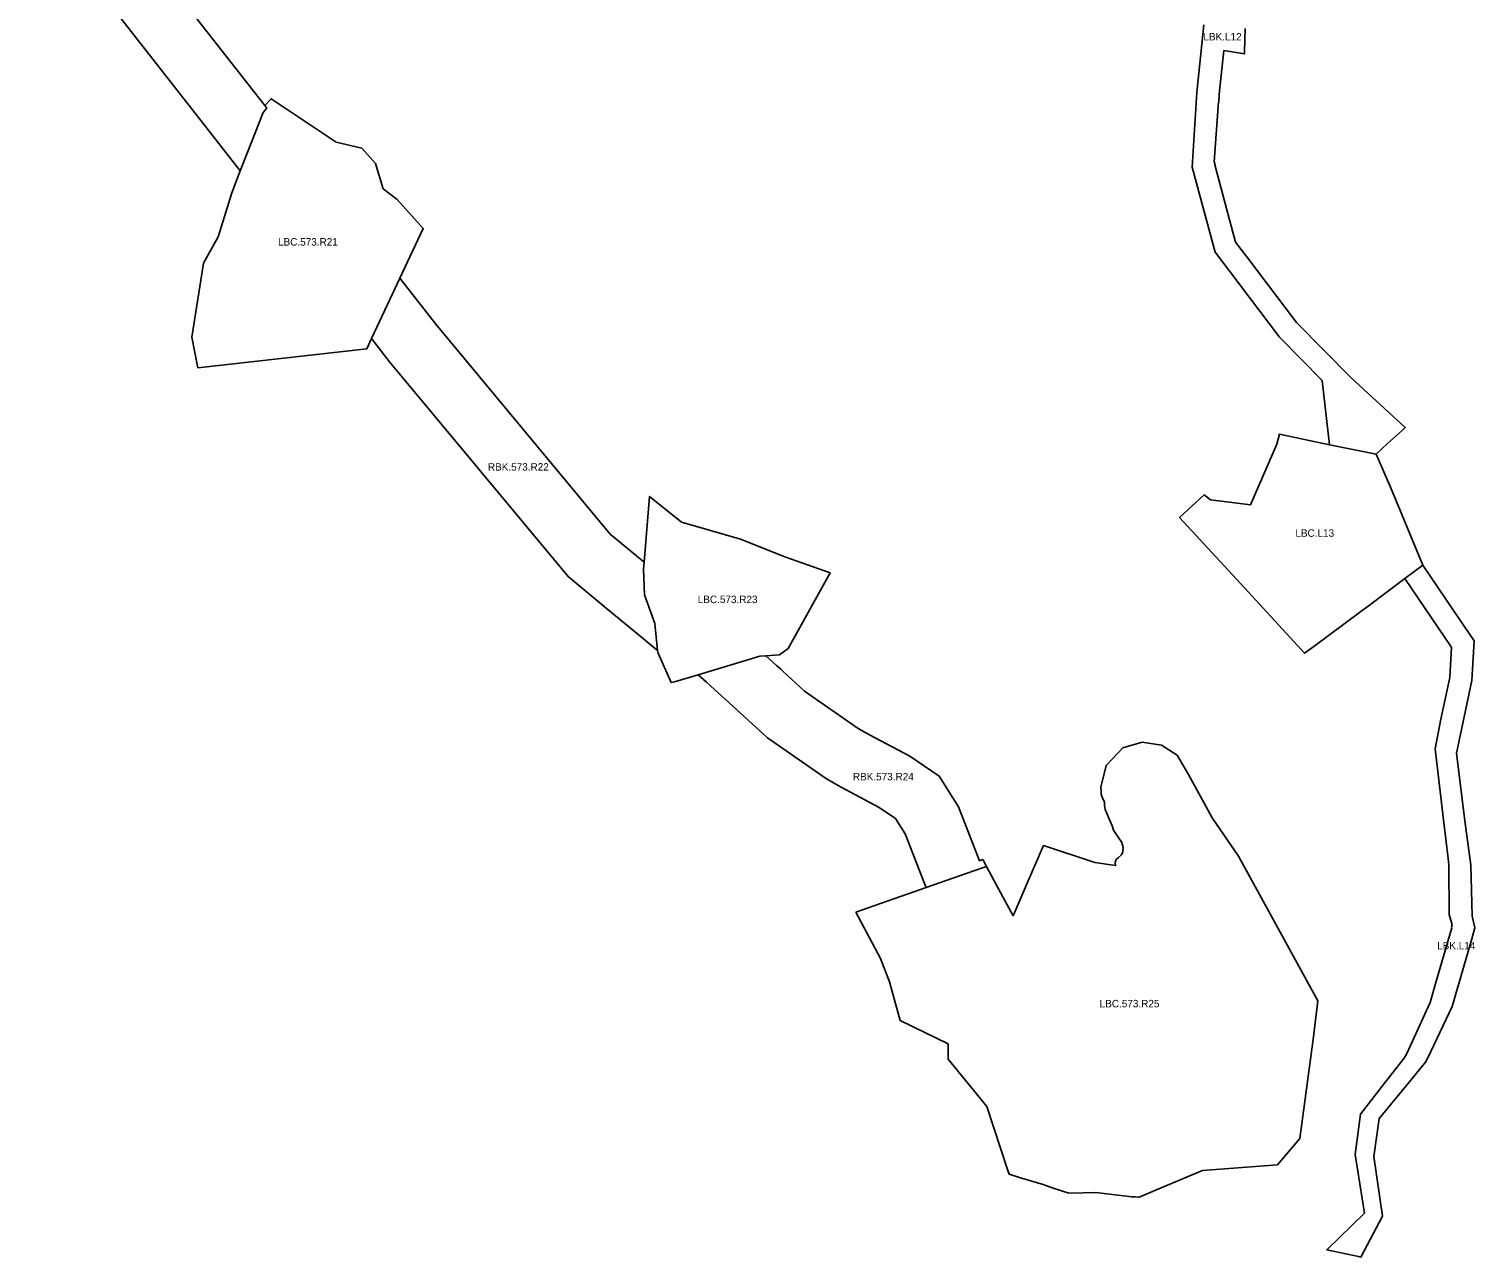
# Model space of a CAD drawing. Extents: x -450188 to -432919, y -1130252 to -1121189.
# Drawn here: x -435642 to -433700, y -1130252 to -1128604 of the extents above; entities that cross this region are included whole.
import ezdxf

# ---------------------------------------------------------------- set-up
doc = ezdxf.new("R2010")
doc.units = 0
for name, color, linetype in [('Vrstva 31', 7, 'Continuous'), ('Vrstva 32', 7, 'Continuous'), ('Vrstva 33', 7, 'Continuous'), ('Vrstva 36', 7, 'Continuous')]:
    doc.layers.add(name, color=color, linetype=linetype)

msp = doc.modelspace()

# ---------------------------------------------------------------- linework, layer by layer
at = {"layer": 'Vrstva 31'}
for p, q in [((-435322.1, -1128710.3), (-435327, -1128715.9)), ((-435324.9, -1128706.8), (-435322.1, -1128710.3))]:
    msp.add_line(p, q, dxfattribs=at)
for points in [[(-435357.8, -1128794.5), (-435405.9, -1128733.1), (-435520.6, -1128586.6), (-435605.8, -1128468.3), (-435641.6, -1128345.5), (-435641.6, -1128210.4), (-435616.7, -1128126.2), (-435604.4, -1128084.8), (-435593.4, -1128047.7), (-435543.9, -1128112.5), (-435527.7, -1128107.5), (-435540, -1128149), (-435561.6, -1128222.1), (-435561.6, -1128334), (-435532.8, -1128432.7), (-435456.6, -1128538.6), (-435342.9, -1128683.8), (-435324.9, -1128706.8)], [(-435327, -1128715.9), (-435348.4, -1128770.6), (-435357.8, -1128794.5)]]:
    msp.add_lwpolyline(points, dxfattribs=at)
at = {"layer": 'Vrstva 32'}
for p, q in [((-435322.1, -1128710.3), (-435324.9, -1128706.8)), ((-435160, -1128973.7), (-435181.5, -1129019.6)), ((-433895.3, -1129161.9), (-433832.7, -1129174.8)), ((-434816.2, -1129328.8), (-434815.5, -1129319.6)), ((-433769.9, -1129323.7), (-433794, -1129341.7))]:
    msp.add_line(p, q, dxfattribs=at)
for points in [[(-435324.9, -1128706.8), (-435316.1, -1128697.7), (-435228.9, -1128756), (-435194.6, -1128763.9), (-435176.1, -1128784.7), (-435165.9, -1128818.5), (-435147.3, -1128832.9), (-435112.2, -1128871.6), (-435143.5, -1128938.4), (-435160, -1128973.7)], [(-435181.5, -1129019.6), (-435187.9, -1129033.1), (-435414.9, -1129058.7), (-435422.9, -1129017.8), (-435410.6, -1128940.9), (-435407, -1128918.3), (-435387.7, -1128882.9), (-435369.2, -1128823.7), (-435357.8, -1128794.5), (-435348.4, -1128770.6), (-435327, -1128715.9), (-435322.1, -1128710.3)], [(-433794, -1129341.7), (-433841.6, -1129377.1), (-433853.2, -1129385.7), (-433916.3, -1129432.7), (-433928.7, -1129441.9), (-433938.2, -1129431.6), (-434009.5, -1129354.1), (-434096.4, -1129259.6), (-434063.4, -1129229.2), (-434055.1, -1129235.9), (-434001.1, -1129242.6), (-433966, -1129161), (-433962.5, -1129148), (-433895.3, -1129161.9)], [(-433832.7, -1129174.8), (-433813.1, -1129218.7), (-433797.9, -1129255.7), (-433769.9, -1129323.7)], [(-434815.5, -1129319.6), (-434808.1, -1129231.4), (-434765.2, -1129265.8), (-434729.4, -1129276.3), (-434685.9, -1129288.7), (-434626.7, -1129312.6), (-434565.6, -1129334.1), (-434622, -1129435.3), (-434633.9, -1129443.9)], [(-434633.9, -1129443.9), (-434651.9, -1129445.2), (-434660.1, -1129445.8), (-434742.9, -1129470.6), (-434774.7, -1129480.1), (-434779.3, -1129481.2), (-434797.1, -1129441), (-434797.4, -1129438.3), (-434801, -1129401.8), (-434814.8, -1129363.2), (-434816.2, -1129328.8)]]:
    msp.add_lwpolyline(points, dxfattribs=at)
msp.add_lwpolyline([(-434531, -1129789.1), (-434436.8, -1129756.2), (-434391.9, -1129740.6), (-434361.2, -1129729.9), (-434355.7, -1129727.9), (-434342.2, -1129753.1), (-434320, -1129794.1), (-434299.6, -1129747.1), (-434279.1, -1129700), (-434210.3, -1129722.7), (-434182.5, -1129726.7), (-434183.1, -1129722.6), (-434181.5, -1129718.7), (-434178.4, -1129715.9), (-434174.4, -1129712.2), (-434172.8, -1129708.3), (-434172.2, -1129702.7), (-434174.1, -1129695.7), (-434179, -1129688.8), (-434185.3, -1129679.1), (-434186.8, -1129673.5), (-434192.4, -1129660.7), (-434196.6, -1129651.5), (-434197.5, -1129645.5), (-434197.5, -1129641), (-434200.2, -1129636.4), (-434201.8, -1129631), (-434201.8, -1129626.7), (-434202.2, -1129621.4), (-434194.9, -1129592.3), (-434172.6, -1129568.7), (-434146.6, -1129561.3), (-434120.6, -1129565), (-434099.6, -1129578.6), (-434084.7, -1129604.6), (-434052.6, -1129662.8), (-434017.3, -1129714.2), (-433911, -1129908.3), (-433916.6, -1129956.8), (-433935.2, -1130093), (-433965.1, -1130128.5), (-434065.8, -1130135.9), (-434126.5, -1130161.3), (-434150.7, -1130171.7), (-434156.2, -1130171.5), (-434160.7, -1130171.3), (-434164.1, -1130171), (-434209, -1130165.3), (-434226, -1130165.9), (-434245, -1130166.6), (-434266.2, -1130159.5), (-434279.8, -1130154.9), (-434310, -1130145.8), (-434325.4, -1130141.1), (-434327.1, -1130135.9), (-434355.1, -1130050.1), (-434407.3, -1129986.6), (-434407.3, -1129966.1), (-434471.5, -1129934.6), (-434486, -1129883), (-434497.9, -1129851.3)], close=True, dxfattribs=at)
at = {"layer": 'Vrstva 33'}
for p, q in [((-435160, -1128973.7), (-435143.5, -1128938.4)), ((-435181.5, -1129019.6), (-435160, -1128973.7)), ((-433794, -1129341.7), (-433769.9, -1129323.7)), ((-434801, -1129401.8), (-434797.4, -1129438.3)), ((-434361.2, -1129729.9), (-434391.9, -1129740.6))]:
    msp.add_line(p, q, dxfattribs=at)
for points in [[(-434008.2, -1128603.5), (-434009.2, -1128634.4), (-434009.3, -1128637.2), (-434037.2, -1128633), (-434043.2, -1128691.5), (-434043.9, -1128701.6), (-434044.3, -1128701.9), (-434049.9, -1128782.1), (-434049.2, -1128784.7), (-434049.3, -1128786.4), (-434021.4, -1128890), (-434006.4, -1128909.9), (-433939.7, -1128998.1), (-433866.2, -1129072), (-433793.5, -1129138.8), (-433797.2, -1129142.2), (-433817.1, -1129160.5), (-433832.7, -1129174.8), (-433895.3, -1129161.9), (-433898.8, -1129130.6), (-433905, -1129075.6), (-433962.4, -1129017.8), (-434030.3, -1128927.9), (-434048.9, -1128903.4), (-434079.6, -1128789.4), (-434073.1, -1128689.1), (-434063.9, -1128598.6)], [(-435143.5, -1128938.4), (-435095.1, -1129000.3), (-434861, -1129282.1), (-434815.5, -1129319.6), (-434816.2, -1129328.8), (-434814.8, -1129363.2), (-434801, -1129401.8)], [(-434797.4, -1129438.3), (-434816.5, -1129422.6), (-434866.4, -1129381.3), (-434917.7, -1129339), (-435157.3, -1129050.5), (-435181.5, -1129019.6)], [(-433703.9, -1129478.2), (-433724.7, -1129575.7), (-433713, -1129670.4), (-433705.7, -1129722.8), (-433705.3, -1129725.8), (-433703.4, -1129794.8), (-433699.8, -1129810.4), (-433704.1, -1129825.2), (-433730.5, -1129915.9), (-433763.3, -1129984.8), (-433766.2, -1129990.7), (-433792.2, -1130022.3), (-433828.6, -1130066.3), (-433835.5, -1130117.3), (-433823.8, -1130197.1), (-433853, -1130252.2), (-433856.1, -1130251.5), (-433898.9, -1130242.4), (-433848.3, -1130193.2), (-433860.7, -1130114.4), (-433853.6, -1130060.5), (-433821.1, -1130018.6), (-433794.9, -1129985.4), (-433791.5, -1129978.8), (-433760, -1129910.7), (-433752.4, -1129883.7), (-433731.1, -1129810.5), (-433731.4, -1129809.3), (-433730.6, -1129806.2), (-433734.6, -1129792.3), (-433735, -1129726.3), (-433735.8, -1129717.4), (-433742.2, -1129665.3), (-433753.5, -1129570.3), (-433745.7, -1129530.3), (-433733.7, -1129474.2), (-433731.4, -1129433.5), (-433731.6, -1129433.2), (-433794, -1129341.7)], [(-433769.9, -1129323.7), (-433728.7, -1129384.3), (-433700.9, -1129425), (-433703.9, -1129478.2)], [(-434742.9, -1129470.6), (-434660.1, -1129445.8), (-434651.9, -1129445.2)], [(-434651.9, -1129445.2), (-434637.7, -1129458.2), (-434632.5, -1129462.9), (-434629.3, -1129465.9), (-434600, -1129492.5), (-434527.9, -1129542.7), (-434512.7, -1129551.3), (-434458.7, -1129579.9), (-434419.1, -1129606.6), (-434393.3, -1129648.1), (-434365, -1129720.3), (-434360.8, -1129718.5), (-434355.7, -1129727.9), (-434361.2, -1129729.9)], [(-434391.9, -1129740.6), (-434436.8, -1129756.2), (-434438.9, -1129750.9), (-434465.1, -1129684.2), (-434478, -1129663.4), (-434500, -1129648.6), (-434551, -1129621.5), (-434570.5, -1129610.5), (-434650, -1129555.2), (-434691.6, -1129517.3), (-434726.6, -1129485.4), (-434731.9, -1129480.5), (-434742.9, -1129470.6)]]:
    msp.add_lwpolyline(points, dxfattribs=at)

# ---------------------------------------------------------------- texts
at = {"layer": 'Vrstva 36'}
for s, p in [('LBK.L12', (-434064.5, -1128619.4)), ('LBC.573.R21', (-435307.1, -1128894.7)), ('RBK.573.R22', (-435025.3, -1129196.7)), ('LBC.L13', (-433941, -1129285.5)), ('LBC.573.R23', (-434743.5, -1129374.5)), ('RBK.573.R24', (-434535.2, -1129612.4)), ('LBK.L14', (-433750.6, -1129839.2)), ('LBC.573.R25', (-434203.8, -1129917))]:
    msp.add_text(s, height=10, dxfattribs=at).set_placement(p)

doc.saveas('drawing.dxf')
